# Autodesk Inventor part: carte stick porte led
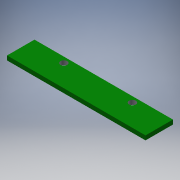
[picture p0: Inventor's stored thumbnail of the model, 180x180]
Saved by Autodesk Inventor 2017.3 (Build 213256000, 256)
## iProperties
Part Number: carte stick porte led
Material: Générique
Document SubType Name: Modeling
Designer: ficho
Density: 1 g/cm^3
Appearance: Par défaut
Author: ficho
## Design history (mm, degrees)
sketch "Esquisse1"
  geometry: L1 (0, 0)-(51.5, 0); L2 (51.5, 0)-(51.5, 10.2); L3 (51.5, 10.2)-(0, 10.2); L4 (0, 10.2)-(0, 0)
  constraints: 8 end point, 2 parallel, 1 horizontal, 1 perpendicular
  dimensions: "d0" = 51.5 distance of L3.end L2.end; "d1" = 10.2 distance of L2.end L1.end
extrude "Extrusion1" new body sketch "Esquisse1" distance "d2" = 1.6; taper "d3" = 0 deg
sketch "Esquisse2"
  geometry: L1 (0.75, 6.24)-(50.75, 6.24); L2 (50.75, 6.24)-(50.75, 1.24); L3 (50.75, 1.24)-(0.75, 1.24); L4 (0.75, 1.24)-(0.75, 6.24); L5 (0, 10.2)-(0, 0) reference; L6 (51.5, 0)-(51.5, 10.2) reference; C1 r 1.25 at (13, 8.146); C2 r 1.25 at (38.5, 8.146)
  constraints: 8 end point, 2 centre point, 2 parallel, 1 horizontal, 1 perpendicular
  dimensions: "d4" = 5 distance between parallel lines of L3 L1; "d5" = 50 distance between parallel lines of L2 L4; "d6" = 0.75 distance between parallel lines of L4 L5; "d7" = 2.5 diameter of C1; "d8" = 2.5 diameter of C2 (= d7); "d9" = 13 distance from line of C1.centre L5; "d10" = 13 distance from line of C2.centre L6 (= d9)
extrude "Extrusion2" cut sketch "Esquisse2" stored distance "d11" = 3; taper "d12" = 0 deg
node "Solide1"
